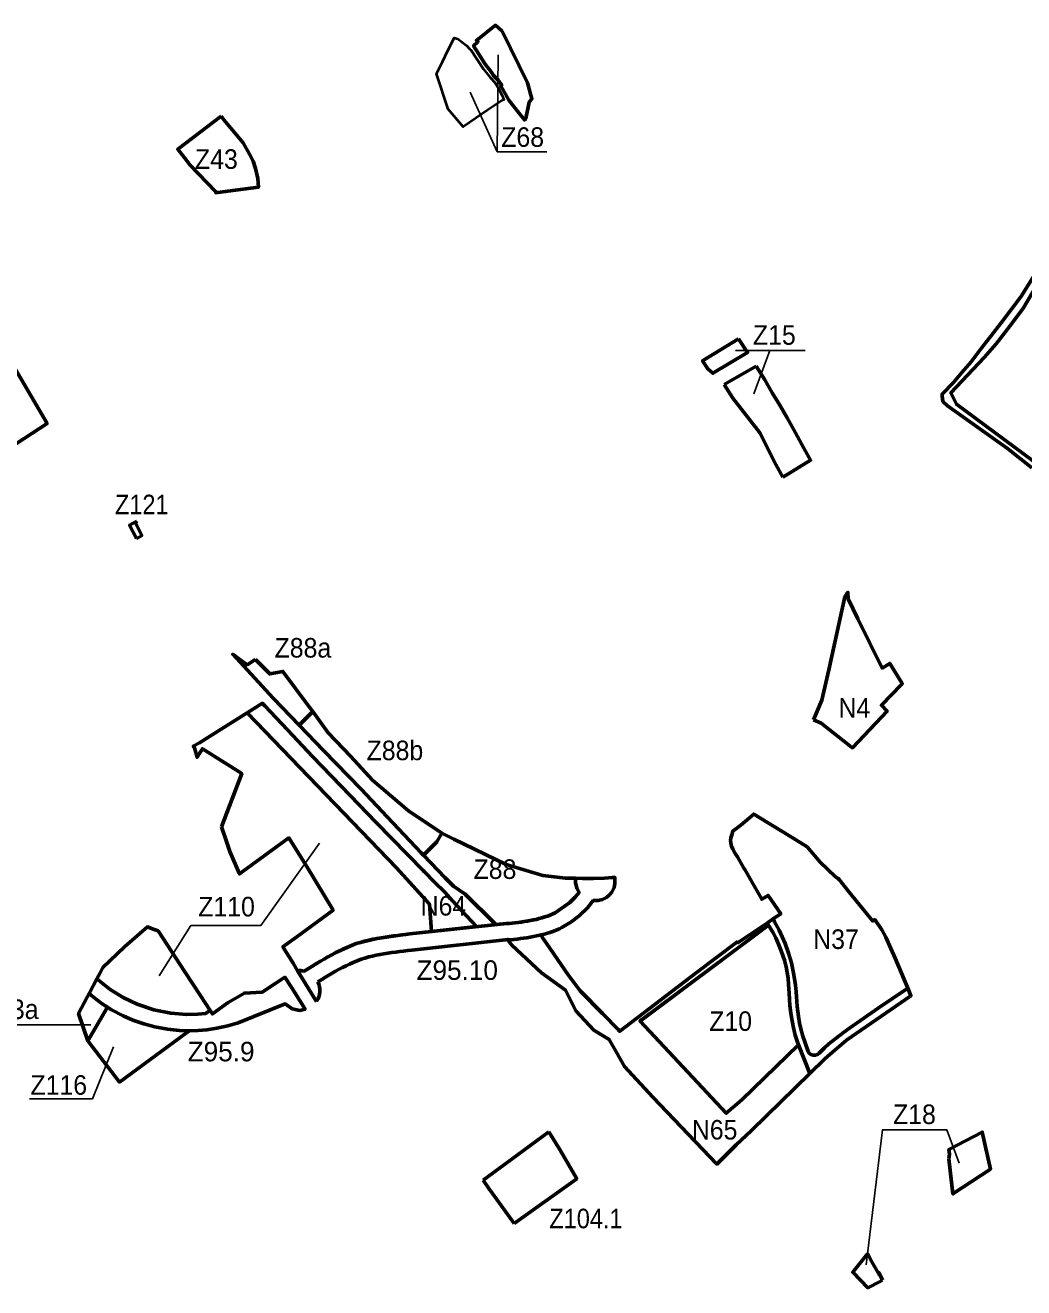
# Model space of a CAD drawing. Extents: x -650277 to -643422, y -1073980 to -1066720.
# Drawn here: x -647467 to -646242, y -1072620 to -1071070 of the extents above; entities that cross this region are included whole.
import ezdxf

# ---------------------------------------------------------------- set-up
doc = ezdxf.new("R2010")
doc.units = 0
doc.header["$LTSCALE"] = 9.6
for name, color, linetype, lineweight in [('1', 7, 'Continuous', 60), ('11', 7, 'Continuous', 60), ('15', 7, 'Continuous', 60), ('2', 7, 'Continuous', 40), ('24', 7, 'Continuous', 60), ('30', 7, 'Continuous', 60), ('35', 7, 'Continuous', 60), ('40', 7, 'Continuous', 60), ('42', 7, 'Continuous', 60), ('45', 7, 'Continuous', 60), ('59', 7, 'Continuous', 25), ('60', 7, 'Continuous', 60), ('63', 7, 'Continuous', 25), ('7', 7, 'Continuous', 60), ('9', 7, 'Continuous', 60)]:
    doc.layers.add(name, color=color, linetype=linetype, lineweight=lineweight)

msp = doc.modelspace()

# ---------------------------------------------------------------- linework, layer by layer
at = {"layer": '1'}
for p, q in [((-646609.21, -1071510.98), (-646570, -1071488.38)), ((-646417.787, -1072612.168), (-646414.77, -1072610.61))]:
    msp.add_line(p, q, dxfattribs=at)
for points in [[(-646591.65, -1071454.91), (-646635.79, -1071481.6), (-646629.37, -1071491.74), (-646623.18, -1071496.99), (-646580.58, -1071471.48)], [(-646606.848, -1072405.785), (-646587.666, -1072389.082), (-646518.208, -1072321.92), (-646519.417, -1072318.408), (-646522.007, -1072309.932), (-646524.282, -1072300.849), (-646526, -1072292.201), (-646527.5, -1072282.657), (-646528.566, -1072273.308), (-646529.182, -1072265.941), (-646529.607, -1072258.124), (-646530.188, -1072247.442), (-646530.892, -1072239.747), (-646531.93, -1072232.861), (-646533.286, -1072226.031), (-646535.344, -1072217.844), (-646536.772, -1072213.218), (-646539.168, -1072206.122), (-646539.168, -1072206.122), (-646542.484, -1072197.985), (-646546.09, -1072190.428), (-646549.793, -1072183.38), (-646554.56, -1072175.629), (-646555.051, -1072174.933), (-646563.299, -1072181.091), (-646710.684, -1072291.133), (-646712.634, -1072292.59)], [(-646333.34, -1072461.67), (-646328.45, -1072504.81), (-646282.47, -1072474.34), (-646292.44, -1072428.89), (-646333.33, -1072450.12), (-646332.68, -1072456.19)]]:
    msp.add_lwpolyline(points, close=True, dxfattribs=at)
for points in [[(-646570, -1071488.38), (-646559.53, -1071505.12), (-646550.23, -1071520.88), (-646541.14, -1071536.3), (-646532.04, -1071551.72), (-646521.8, -1071570.34), (-646511.47, -1071589.11), (-646503.31, -1071603.95), (-646531.2, -1071621.07), (-646537.28, -1071624.8)], [(-646537.28, -1071624.8), (-646545.89, -1071609.07), (-646555.78, -1071589.66), (-646565.17, -1071570.4), (-646598.63, -1071527.8), (-646609.21, -1071510.98)], [(-647184.81, -1071848.61), (-647185.62, -1071849.12), (-647194.96, -1071854.93), (-647205.62, -1071847.24), (-647212.66, -1071842.15), (-647163.08, -1071896.13), (-647131.146, -1071929.146)], [(-647131.146, -1071929.146), (-647114.479, -1071912.479), (-647118.79, -1071906.59), (-647151.07, -1071863.08), (-647167.15, -1071866.22), (-647184.81, -1071848.61)], [(-646996.8, -1072034.35), (-647040.89, -1071996.58), (-647067.53, -1071967.54), (-647095.51, -1071938.39), (-647114.479, -1071912.479), (-647131.146, -1071929.146), (-647101.07, -1071960.24)], [(-647101.07, -1071960.24), (-647055.16, -1072007.74), (-647023.04, -1072041.63), (-646981.35, -1072085.77), (-646978.602, -1072088.66), (-646962.041, -1072072.379), (-646956.04, -1072061.95), (-646996.8, -1072034.35)], [(-646420.36, -1072601.78), (-646427.95, -1072588.07), (-646432.57, -1072579.75), (-646433.36, -1072578.45), (-646451.458, -1072601.008), (-646433.024, -1072620.04), (-646417.787, -1072612.168)], [(-646414.77, -1072610.61), (-646419.11, -1072602.03), (-646419.47, -1072601.31), (-646419.02, -1072604.18), (-646420.36, -1072601.78)]]:
    msp.add_lwpolyline(points, dxfattribs=at)
at = {"layer": '1', "lineweight": 53}
for points in [[(-647330.34, -1071678.82), (-647339.211, -1071683.431), (-647330.73, -1071700.09)], [(-647330.73, -1071700.09), (-647324.21, -1071696.2), (-647331.65, -1071681.7), (-647330.34, -1071678.82)]]:
    msp.add_lwpolyline(points, dxfattribs=at)
at = {"layer": '11'}
msp.add_lwpolyline([(-646066.165, -1071422.155), (-646153.5, -1071383.85), (-646208.577, -1071360.044), (-646241.68, -1071416.887), (-646258.487, -1071439.265), (-646275.615, -1071460.886), (-646289.976, -1071477.514), (-646330.914, -1071521.11), (-646324, -1071535), (-646217.978, -1071613.552), (-646211.407, -1071606.247), (-646156.471, -1071545.166), (-646094.063, -1071471.007)], close=True, dxfattribs=at)
at = {"layer": '15'}
for points in [[(-646217.978, -1071613.552), (-646324, -1071535), (-646330.914, -1071521.11), (-646289.976, -1071477.514), (-646275.615, -1071460.886), (-646275.615, -1071460.886), (-646258.487, -1071439.265), (-646241.68, -1071416.887), (-646208.577, -1071360.044)], [(-646223.77, -1071369.24), (-646245.1, -1071403.04), (-646269.2, -1071435.22), (-646281.99, -1071451.4), (-646283.52, -1071453.34), (-646293.87, -1071466.43), (-646306.14, -1071482.86), (-646317.52, -1071496.12), (-646327.97, -1071508.29), (-646341.88, -1071522.81), (-646341.66, -1071524.87), (-646340.93, -1071531.64), (-646335.3, -1071537.05), (-646261.46, -1071589.38), (-646231.43, -1071613.06)]]:
    msp.add_lwpolyline(points, dxfattribs=at)
msp.add_lwpolyline([(-646529.182, -1072265.941), (-646528.566, -1072273.308), (-646527.5, -1072282.657), (-646526, -1072292.201), (-646524.282, -1072300.849), (-646522.007, -1072309.932), (-646519.417, -1072318.408), (-646518.208, -1072321.92), (-646504.244, -1072357.026), (-646485.656, -1072338.908), (-646473.069, -1072327.765), (-646465.227, -1072321.127), (-646459.03, -1072316.137), (-646380.12, -1072261.44), (-646384.056, -1072252.138), (-646420.085, -1072276.737), (-646455.557, -1072301.131), (-646462.79, -1072306.784), (-646480.923, -1072320.667), (-646486.273, -1072325.526), (-646492.813, -1072332.07), (-646494.794, -1072333.558), (-646497.569, -1072334.55), (-646500.244, -1072334.45), (-646503.018, -1072333.459), (-646504.802, -1072331.971), (-646506.189, -1072329.889), (-646509.954, -1072319.377), (-646512.729, -1072311.048), (-646515.305, -1072301.925), (-646516.692, -1072294.983), (-646518.079, -1072287.051), (-646519.756, -1072274.861), (-646521.051, -1072256.707), (-646521.646, -1072248.378), (-646523.628, -1072235.883), (-646526.798, -1072221.011), (-646530.167, -1072209.31), (-646534.527, -1072197.411), (-646541.822, -1072181.102), (-646547.606, -1072170.835), (-646548.676, -1072166.737), (-646556.693, -1072172.16), (-646555.051, -1072174.933), (-646554.56, -1072175.629), (-646549.793, -1072183.38), (-646546.09, -1072190.428), (-646542.484, -1072197.985), (-646539.168, -1072206.122), (-646536.772, -1072213.218), (-646535.344, -1072217.844), (-646533.286, -1072226.031), (-646531.93, -1072232.861), (-646530.892, -1072239.747), (-646530.188, -1072247.442), (-646529.607, -1072258.124)], close=True, dxfattribs=at)
at = {"layer": '2'}
msp.add_lwpolyline([(-646921.668, -1071098.861), (-646920.54, -1071099.98), (-646904.64, -1071123.54), (-646896.62, -1071133.93), (-646890.59, -1071140.39), (-646887.07, -1071145.66), (-646881.97, -1071155.84), (-646879.91, -1071161.24), (-646881.68, -1071161.83), (-646899.85, -1071173.89), (-646929.64, -1071194.58), (-646948.286, -1071172.534), (-646962.471, -1071129.325), (-646955.138, -1071114.466), (-646951.831, -1071107.765), (-646951.831, -1071107.765), (-646940.67, -1071085.15), (-646940.67, -1071085.15), (-646936.51, -1071086.33), (-646925.88, -1071094.68)], close=True, dxfattribs=at)
at = {"layer": '24'}
for points in [[(-647226.41, -1072054.11), (-647219.64, -1072074.29), (-647216.23, -1072084.14), (-647204.78, -1072110.92), (-647204.38, -1072111.87), (-647143.76, -1072067.69), (-647122.33, -1072101.34), (-647089.54, -1072156.53), (-647134.17, -1072188.95), (-647151.05, -1072201.21), (-647138.65, -1072221.5), (-647133, -1072230.754), (-647124.81, -1072231.168), (-647104.989, -1072219.005), (-647082.249, -1072206.591), (-647060.973, -1072197.439), (-647035.515, -1072191.104), (-647010.148, -1072187.308), (-646995.137, -1072185.597), (-646968.503, -1072182.672), (-646971.283, -1072148.82), (-647011.762, -1072104.502), (-647194.903, -1071913.941), (-647238.1, -1071941), (-647245.71, -1071945.77), (-647253.67, -1071950.76), (-647261.12, -1071954.82), (-647259.7, -1071957.06), (-647256.53, -1071968.64), (-647253.85, -1071964.38), (-647249.92, -1071958.12), (-647201.53, -1071988.71)], [(-647390.58, -1072316.75), (-647366.505, -1072275.41), (-647372.858, -1072271.363), (-647383.813, -1072263.219), (-647389.072, -1072258.845), (-647391.3, -1072263.04), (-647401.88, -1072283.4)], [(-647390.58, -1072316.75), (-647351.86, -1072367.52), (-647269.52, -1072307.17), (-647265.793, -1072304.439), (-647271.395, -1072304.452), (-647278.108, -1072304.147), (-647292.715, -1072302.646), (-647308.157, -1072299.786), (-647321.953, -1072296.073), (-647335.382, -1072291.341), (-647347.369, -1072286.111), (-647361.521, -1072278.584), (-647366.505, -1072275.41)]]:
    msp.add_lwpolyline(points, close=True, dxfattribs=at)
msp.add_arc((-646767.624, -1072120.384), 24.428, 264.28146, 264.89913, dxfattribs=at)
at = {"layer": '30'}
for points in [[(-646824.42, -1072428.58), (-646878.91, -1072468.54), (-646905.18, -1072487.8)], [(-646867.283, -1072540.984), (-646791.569, -1072487.198), (-646790.354, -1072486.136), (-646810.77, -1072451.09), (-646824.42, -1072428.58)], [(-646905.18, -1072487.8), (-646898.1, -1072498.02), (-646893.64, -1072504.45), (-646867.283, -1072540.984)]]:
    msp.add_lwpolyline(points, dxfattribs=at)
at = {"layer": '35'}
msp.add_lwpolyline([(-647246.563, -1072270.214), (-647251.85, -1072262.12), (-647271.38, -1072232.23), (-647304.32, -1072181.81), (-647310.33, -1072179.58), (-647317.33, -1072176.99), (-647345.42, -1072201.58), (-647372.1, -1072226.89), (-647375.551, -1072233.387), (-647379.422, -1072240.675), (-647363.317, -1072253.632), (-647347.382, -1072263.623), (-647330.032, -1072271.935), (-647309.416, -1072278.875), (-647288.769, -1072283.003), (-647269.579, -1072284.489), (-647255.671, -1072284.192), (-647246.206, -1072283.328), (-647240.55, -1072279.42)], close=True, dxfattribs=at)
at = {"layer": '40'}
msp.add_lwpolyline([(-646507.28, -1072078.4), (-646530.073, -1072064.559), (-646573.05, -1072038.46), (-646588.75, -1072052.06), (-646598.827, -1072059.244), (-646599.86, -1072063.71), (-646601, -1072067.55), (-646601.42, -1072071.01), (-646601.16, -1072074.07), (-646600.8, -1072075.94), (-646600.22, -1072077.86), (-646598.67, -1072081.55), (-646595.86, -1072086.82), (-646593.13, -1072091.01), (-646591.02, -1072094.4), (-646585.08, -1072104.81), (-646583.9, -1072106.42), (-646577.41, -1072117.76), (-646577.08, -1072118.7), (-646563.11, -1072143.03), (-646555.49, -1072138.17), (-646539.94, -1072160.83), (-646548.676, -1072166.737), (-646547.606, -1072170.835), (-646541.822, -1072181.102), (-646534.527, -1072197.411), (-646530.167, -1072209.31), (-646526.798, -1072221.011), (-646523.628, -1072235.883), (-646521.646, -1072248.378), (-646521.051, -1072256.707), (-646519.756, -1072274.861), (-646518.079, -1072287.051), (-646516.692, -1072294.983), (-646515.305, -1072301.925), (-646512.729, -1072311.048), (-646509.954, -1072319.377), (-646506.189, -1072329.889), (-646504.802, -1072331.971), (-646503.018, -1072333.459), (-646500.244, -1072334.45), (-646497.569, -1072334.55), (-646494.794, -1072333.558), (-646492.813, -1072332.07), (-646486.273, -1072325.526), (-646480.923, -1072320.667), (-646462.79, -1072306.784), (-646455.557, -1072301.131), (-646420.085, -1072276.737), (-646384.056, -1072252.138), (-646391.77, -1072233.91), (-646399.6, -1072215.39), (-646404.67, -1072203.42), (-646410.68, -1072189.36), (-646415.84, -1072180.43), (-646424.56, -1072167.96), (-646426.98, -1072169.74), (-646455.75, -1072134.29), (-646468.35, -1072118.76), (-646469.41, -1072117.44), (-646472.72, -1072115.38), (-646491.69, -1072097.45)], close=True, dxfattribs=at)
at = {"layer": '42'}
msp.add_lwpolyline([(-647011.762, -1072104.502), (-646971.283, -1072148.82), (-646968.503, -1072182.672), (-646942.928, -1072179.864), (-646913.373, -1072176.618), (-646931.653, -1072156.802), (-646942.78, -1072144.74), (-646952.48, -1072134.22), (-646964.8, -1072121.83), (-646977.59, -1072108.96), (-646978.45, -1072108.09), (-647036.8, -1072048.41), (-647068.31, -1072015.68), (-647114.59, -1071967.77), (-647145.38, -1071935), (-647173.14, -1071905.45), (-647174.57, -1071904.06), (-647176.32, -1071902.3), (-647194.903, -1071913.941)], close=True, dxfattribs=at)
at = {"layer": '45'}
msp.add_lwpolyline([(-646594.606, -1072444.422), (-646575.792, -1072426.789), (-646504.244, -1072357.026), (-646518.208, -1072321.92), (-646587.666, -1072389.082), (-646606.848, -1072405.785), (-646712.634, -1072292.59), (-646563.299, -1072181.091), (-646555.051, -1072174.933), (-646556.693, -1072172.16), (-646592.2, -1072196.17), (-646593.85, -1072195.48), (-646643.55, -1072233.5), (-646737.449, -1072305.019), (-646738.951, -1072303.49), (-646758.684, -1072283.41), (-646785.958, -1072255.505), (-646800.76, -1072235.668), (-646826.893, -1072197.582), (-646832.718, -1072189.697), (-646834.279, -1072186.818), (-646833.373, -1072186.562), (-646835.538, -1072187.097), (-646839.556, -1072187.988), (-646843.569, -1072188.789), (-646847.575, -1072189.507), (-646851.567, -1072190.155), (-646855.545, -1072190.741), (-646859.506, -1072191.276), (-646863.448, -1072191.771), (-646867.371, -1072192.234), (-646871.271, -1072192.675), (-646874.517, -1072192.471), (-646875.509, -1072192.58), (-646870.21, -1072199.51), (-646833.75, -1072233.32), (-646803.98, -1072254.74), (-646791.59, -1072279.78), (-646769.24, -1072303.65), (-646750.58, -1072315.02), (-646750.12, -1072315.82), (-646742.32, -1072329.62), (-646731.82, -1072348.2), (-646696.83, -1072385.81), (-646618.158, -1072468.098)], close=True, dxfattribs=at)
at = {"layer": '59'}
msp.add_lwpolyline([(-646827, -1071225), (-646888, -1071225), (-646921, -1071152)], dxfattribs=at)
at = {"layer": '60'}
msp.add_line((-646978.602, -1072088.66), (-646951.95, -1072116.84), dxfattribs=at)
for points in [[(-646790.432, -1072129.195), (-646791.977, -1072122.305), (-646791.84, -1072117.172), (-646804.27, -1072116.98), (-646832.01, -1072113.66), (-646876.83, -1072100.12), (-646941.054, -1072069.172), (-646956.04, -1072061.95), (-646962.041, -1072072.379), (-646978.602, -1072088.66)], [(-646951.95, -1072116.84), (-646941.45, -1072126.84), (-646927.14, -1072136.74), (-646891.05, -1072172.79), (-646890.044, -1072174.056), (-646876.712, -1072172.592), (-646873.495, -1072172.799), (-646862.09, -1072171.444), (-646840.102, -1072167.623), (-646825.169, -1072163.164), (-646816.74, -1072159.571), (-646799, -1072147), (-646792.58, -1072140.847), (-646787.481, -1072134.643), (-646790.432, -1072129.195)], [(-646816.74, -1072159.571), (-646799, -1072147), (-646792.58, -1072140.847), (-646787.481, -1072134.643), (-646790.343, -1072129.36), (-646791.977, -1072122.305), (-646791.84, -1072117.172), (-646783.449, -1072117.302), (-646769.668, -1072117.517), (-646756.298, -1072117), (-646746.547, -1072116.221), (-646743.596, -1072115.985), (-646743.411, -1072123.612), (-646744.554, -1072128.415), (-646747.39, -1072134.069), (-646750.164, -1072137.467), (-646753.929, -1072140.612), (-646758.736, -1072143.137), (-646763.959, -1072144.535), (-646770.057, -1072144.677), (-646777.129, -1072153.576), (-646787.223, -1072163.402), (-646797.713, -1072171.151), (-646808.466, -1072177.78)], [(-647124.81, -1072231.168), (-647113.646, -1072224.274), (-647109.342, -1072221.634), (-647104.989, -1072219.005), (-647100.583, -1072216.405), (-647096.114, -1072213.845), (-647091.574, -1072211.346), (-647086.955, -1072208.921), (-647082.249, -1072206.591), (-647077.456, -1072204.373), (-647072.72, -1072202.352), (-647060.973, -1072197.439), (-647055.906, -1072195.893), (-647050.82, -1072194.5), (-647045.722, -1072193.245), (-647040.618, -1072192.117), (-647035.515, -1072191.104), (-647030.417, -1072190.192), (-647025.33, -1072189.37), (-647020.254, -1072188.623), (-647015.192, -1072187.939), (-647010.148, -1072187.308), (-647005.124, -1072186.715), (-647000.12, -1072186.148), (-646995.137, -1072185.597), (-646876.712, -1072172.592), (-646873.495, -1072172.799), (-646869.667, -1072172.366), (-646865.866, -1072171.917), (-646862.09, -1072171.444), (-646858.343, -1072170.937), (-646854.627, -1072170.389), (-646850.941, -1072169.791), (-646847.291, -1072169.137), (-646843.678, -1072168.416), (-646840.102, -1072167.623), (-646836.573, -1072166.751), (-646833.091, -1072165.791), (-646829.66, -1072164.739), (-646826.287, -1072163.588), (-646822.975, -1072162.332), (-646819.733, -1072160.968), (-646816.74, -1072159.571)], [(-646808.466, -1072177.78), (-646811.621, -1072179.254), (-646815.549, -1072180.906), (-646819.509, -1072182.408), (-646823.496, -1072183.769), (-646827.501, -1072184.997), (-646831.517, -1072186.103), (-646835.538, -1072187.097), (-646839.556, -1072187.988), (-646843.569, -1072188.789), (-646847.575, -1072189.507), (-646851.567, -1072190.155), (-646855.545, -1072190.741), (-646859.506, -1072191.276), (-646863.448, -1072191.771), (-646867.371, -1072192.234), (-646871.271, -1072192.675), (-646874.517, -1072192.471), (-646992.937, -1072205.475), (-646997.894, -1072206.024), (-647002.826, -1072206.583), (-647007.734, -1072207.162), (-647012.612, -1072207.773), (-647017.46, -1072208.427), (-647022.278, -1072209.136), (-647027.061, -1072209.91), (-647031.807, -1072210.758), (-647036.512, -1072211.693), (-647041.174, -1072212.723), (-647045.786, -1072213.858), (-647050.344, -1072215.107), (-647054.841, -1072216.479), (-647064.868, -1072220.746), (-647069.33, -1072222.651), (-647073.611, -1072224.631), (-647077.867, -1072226.739), (-647082.102, -1072228.962), (-647086.322, -1072231.285), (-647090.531, -1072233.695), (-647094.737, -1072236.177), (-647098.944, -1072238.718), (-647103.164, -1072241.306), (-647108.131, -1072244.373)], [(-647109.812, -1072268.588), (-647110.55, -1072267.42), (-647119.07, -1072253.56), (-647128.07, -1072238.83), (-647133, -1072230.754)]]:
    msp.add_lwpolyline(points, dxfattribs=at)
msp.add_lwpolyline([(-647265.793, -1072304.439), (-647255.16, -1072304.123), (-647244.428, -1072303.192), (-647232.368, -1072301.4), (-647218.5, -1072298.335), (-647205.975, -1072294.599), (-647148.171, -1072271.47), (-647139.697, -1072277.484), (-647130.12, -1072279.44), (-647123.774, -1072277.899), (-647141.05, -1072250.54), (-647148.71, -1072238.76), (-647148.71, -1072238.76), (-647160.91, -1072246.82), (-647176.7, -1072257.24), (-647198.3, -1072258.09), (-647218.35, -1072269.67), (-647237.6, -1072283.78), (-647240.55, -1072279.42), (-647246.206, -1072283.328), (-647255.671, -1072284.192), (-647269.579, -1072284.489), (-647288.769, -1072283.003), (-647309.416, -1072278.875), (-647330.032, -1072271.935), (-647347.382, -1072263.623), (-647363.317, -1072253.632), (-647379.422, -1072240.675), (-647389.072, -1072258.845), (-647383.813, -1072263.219), (-647372.858, -1072271.363), (-647361.521, -1072278.584), (-647347.369, -1072286.111), (-647335.382, -1072291.341), (-647321.953, -1072296.073), (-647308.157, -1072299.786), (-647292.715, -1072302.646), (-647278.108, -1072304.147), (-647271.395, -1072304.452), (-647265.793, -1072304.439)], close=True, dxfattribs=at)
for start, end in [(77.44425, 96.77054), (326.23773, 25.81772)]:
    msp.add_arc((-647130.12, -1072255.012), 24.428, start, end, dxfattribs=at)
at = {"layer": '63'}
for p, q in [((-646887, -1071106), (-646888, -1071225)), ((-646510.087, -1071469.269), (-646595.257, -1071469.269)), ((-646572.844, -1071522.353), (-646553.419, -1071469.269)), ((-647525, -1072297), (-647387, -1072297))]:
    msp.add_line(p, q, dxfattribs=at)
for points in [[(-647303, -1072237), (-647264, -1072175), (-647178, -1072175), (-647106, -1072074)], [(-647462, -1072388), (-647385, -1072388), (-647359, -1072324)], [(-646321, -1072467), (-646336, -1072426), (-646415, -1072426), (-646435, -1072592)]]:
    msp.add_lwpolyline(points, dxfattribs=at)
at = {"layer": '7'}
for points in [[(-646453.04, -1071956.3), (-646451.87, -1071956.88), (-646409.4, -1071912.17), (-646416.2, -1071904.81), (-646391.83, -1071879.32), (-646390.732, -1071878.171), (-646405.99, -1071853.26), (-646415.46, -1071859.05), (-646445.115, -1071798.418), (-646456.96, -1071774.2), (-646457.52, -1071765.98), (-646461.09, -1071771.76), (-646480.81, -1071861.18), (-646489.34, -1071898.61), (-646499.741, -1071922.455)], [(-646499.741, -1071922.455), (-646490.111, -1071926.754), (-646453.04, -1071956.3)]]:
    msp.add_lwpolyline(points, dxfattribs=at)
at = {"layer": '9'}
for points in [[(-646881.89, -1071077.03), (-646890.12, -1071069.67), (-646913.49, -1071088.22), (-646911.58, -1071089.9), (-646917.04, -1071094.75), (-646910.53, -1071105.18), (-646902.62, -1071117.58), (-646895.56, -1071126.84), (-646892.339, -1071131.481), (-646886.78, -1071137.25), (-646882.37, -1071143.39), (-646883.63, -1071144.15), (-646873.89, -1071161.58), (-646861.58, -1071177.05), (-646854.49, -1071185.87), (-646852.86, -1071183.98), (-646848.58, -1071163.95), (-646845.39, -1071159.98), (-646850.93, -1071140.54)], [(-647226.895, -1071181.511), (-647280.14, -1071221.92), (-647268.52, -1071236.78), (-647265.15, -1071241.1), (-647233.34, -1071274.07), (-647233.64, -1071275.42), (-647218.75, -1071273.32), (-647181.12, -1071268.66), (-647181.99, -1071257.66), (-647184.58, -1071245.67), (-647187.68, -1071236.74), (-647192.29, -1071228.1), (-647199.82, -1071213.98), (-647223.46, -1071185.83)], [(-647497.04, -1071595.66), (-647440.67, -1071558.93), (-647492.3, -1071470), (-647495.85, -1071471.06), (-647558.654, -1071489.738)]]:
    msp.add_lwpolyline(points, close=True, dxfattribs=at)

# ---------------------------------------------------------------- texts
at = {"layer": '59', "width": 0.95}
msp.add_text('Z68', height=24, dxfattribs=at).set_placement((-646883, -1071219))
at = {"layer": '63'}
for s, width, p in [('Z43', 0.95, (-647259, -1071246)), ('Z15', 0.95, (-646574, -1071462)), ('Z121', 0.9, (-647357.291, -1071670.187)), ('Z88a', 0.95, (-647161.291, -1071846.187)), ('N4', 0.95, (-646469, -1071920)), ('Z88b', 0.95, (-647048.291, -1071972.187)), ('Z88', 0.95, (-646917, -1072118)), ('Z110', 0.95, (-647255, -1072164)), ('N64', 0.95, (-646982, -1072163)), ('N37', 0.95, (-646500, -1072204)), ('N63a', 0.95, (-647524, -1072290)), ('Z10', 0.95, (-646627.672, -1072304.645)), ('Z116', 0.95, (-647461, -1072383)), ('Z18', 0.95, (-646402, -1072419)), ('N65', 0.95, (-646649, -1072438)), ('Z104.1', 0.9, (-646824, -1072547))]:
    msp.add_text(s, height=24, dxfattribs=dict(at, width=width)).set_placement(p)
for s, p in [('Z95.10', (-646987, -1072242)), ('Z95.9', (-647268, -1072342))]:
    msp.add_text(s, height=24, dxfattribs=at).set_placement(p)

doc.saveas('drawing.dxf')
